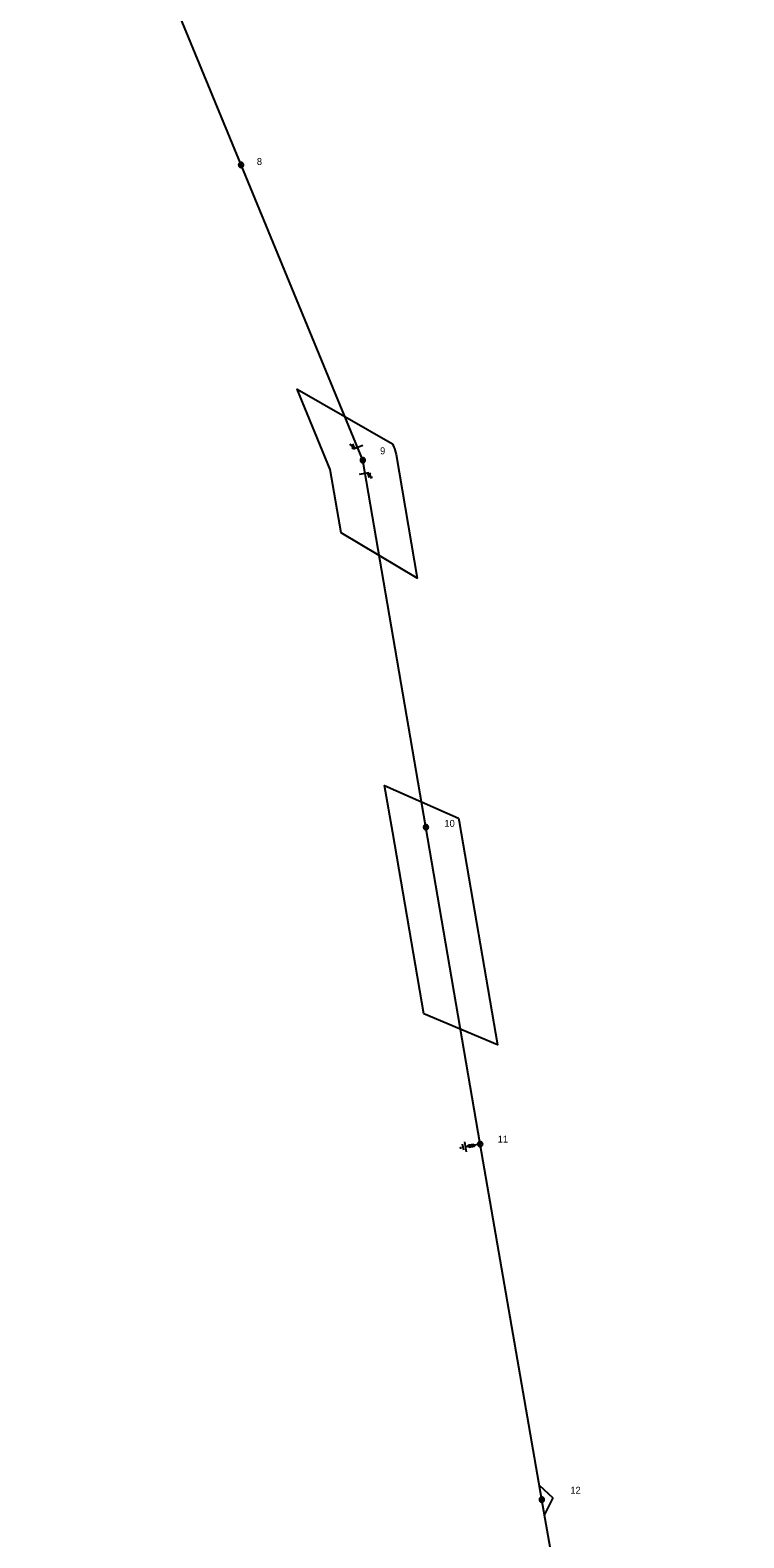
# Model space of a CAD drawing. Extents: x -788491 to -785797, y -1154753 to -1152002.
# Drawn here: x -786883.8 to -786703.8, y -1154288.7 to -1153908.5 of the extents above; entities that cross this region are included whole.
import ezdxf

# ---------------------------------------------------------------- set-up
doc = ezdxf.new("R2010")
doc.units = 0
for name, color, linetype in [('Vrstva 13', 7, 'Continuous'), ('Vrstva 14', 7, 'Continuous'), ('Vrstva 15', 7, 'Continuous'), ('Vrstva 16', 7, 'Continuous'), ('Vrstva 18', 7, 'Continuous'), ('Vrstva 2', 7, 'Continuous'), ('Vrstva 35', 7, 'Continuous'), ('Vrstva 52', 7, 'Continuous')]:
    doc.layers.add(name, color=color, linetype=linetype)

# ---------------------------------------------------------------- blocks, each defined once
blk = doc.blocks.new('VN840')
at = {"layer": 'Vrstva 15'}
for points in [[(-0.01, 1.41), (-0.01, -1.09)], [(-1.51, -1.24), (-1.51, -1.15)], [(-1.48, -1.35), (-1.51, -1.24)], [(-1.33, -1.42), (-1.48, -1.35)], [(-1.27, -1.42), (-1.33, -1.42)], [(-1.13, -1.35), (-1.27, -1.42)], [(-1.09, -1.24), (-1.13, -1.35)], [(-1.09, -0.59), (-1.09, -1.24)], [(-0.68, -0.59), (-0.68, -1.42)], [(-0.68, -1.11), (-0.27, -0.59)], [(-0.54, -0.94), (-0.2, -1.42)]]:
    blk.add_lwpolyline(points, dxfattribs=at)
blk = doc.blocks.new('VN860')
at = {"layer": 'Vrstva 15'}
for points in [[(-3.74, 0), (0.01, 2.82)], [(0.01, 2.82), (3.76, 0)]]:
    blk.add_lwpolyline(points, dxfattribs=at)
blk = doc.blocks.new('VN440')
at = {"layer": 'Vrstva 2'}
for points in [[(1.22, 0), (1.21, 0.13), (1.19, 0.25), (1.16, 0.38), (1.11, 0.5), (1.05, 0.61), (0.98, 0.72), (0.9, 0.82), (0.81, 0.91), (0.71, 0.99), (0.6, 1.06), (0.49, 1.12), (0.37, 1.16), (0.25, 1.2), (0.12, 1.22), (-0.01, 1.22), (-0.14, 1.22), (-0.26, 1.2), (-0.39, 1.16), (-0.51, 1.12), (-0.62, 1.06), (-0.73, 0.99), (-0.83, 0.91), (-0.92, 0.82), (-1, 0.72), (-1.07, 0.61), (-1.13, 0.5), (-1.18, 0.38), (-1.21, 0.25), (-1.23, 0.13), (-1.24, 0), (-1.23, -0.13), (-1.21, -0.26), (-1.18, -0.38), (-1.13, -0.5), (-1.07, -0.62), (-1, -0.73), (-0.92, -0.83), (-0.83, -0.92), (-0.73, -1), (-0.62, -1.07), (-0.51, -1.13), (-0.39, -1.17), (-0.26, -1.2), (-0.14, -1.23), (-0.01, -1.23), (0.12, -1.23), (0.25, -1.2), (0.37, -1.17), (0.49, -1.13), (0.6, -1.07), (0.71, -1), (0.81, -0.92), (0.9, -0.83), (0.98, -0.73), (1.05, -0.62), (1.11, -0.5), (1.16, -0.38), (1.19, -0.26), (1.21, -0.13), (1.22, 0)], [(-1.24, 0), (1.22, 0)], [(-1.18, -0.34), (1.1, -0.34)], [(-1.01, -0.63), (0.97, -0.63)], [(-0.74, -0.92), (0.68, -0.92)]]:
    blk.add_lwpolyline(points, dxfattribs=at)
blk = doc.blocks.new('VN820')
at = {"layer": 'Vrstva 13'}
for points in [[(0, 0), (0, -2.1)], [(-0.32, -1.63), (0.34, -1.63)], [(-0.32, -2.95), (-0.32, -1.63)], [(0.34, -2.95), (-0.32, -2.95)], [(0, -2.1), (-0.12, -1.86)], [(0, -2.1), (0.12, -1.86)], [(0, -2.95), (0, -3.75)], [(0.34, -1.63), (0.34, -2.95)]]:
    blk.add_lwpolyline(points, dxfattribs=at)
blk = doc.blocks.new('VN810')
at = {"layer": 'Vrstva 14'}
for points in [[(1.25, -3.75), (-1.25, -3.75)], [(0, -1.25), (0, -3.75)], [(0.77, -4.37), (-0.8, -4.37)], [(0, -5), (-0.25, -5)], [(0.27, -5), (0, -5)]]:
    blk.add_lwpolyline(points, dxfattribs=at)

msp = doc.modelspace()

# ---------------------------------------------------------------- linework, layer by layer
at = {"layer": 'Vrstva 35'}
for points in [[(-786792.43, -1154012.8), (-786792.06, -1154013.7), (-786791.93, -1154014.04), (-786791.54, -1154015.48), (-786786.17, -1154046.72), (-786805.39, -1154035.24), (-786808.13, -1154019.31), (-786816.49, -1153999.06)], [(-786775.77, -1154107.18), (-786775.62, -1154108.05), (-786765.97, -1154164.35), (-786784.56, -1154156.52), (-786792.37, -1154110.92), (-786794.43, -1154098.97)]]:
    msp.add_lwpolyline(points, close=True, dxfattribs=at)
at = {"layer": 'Vrstva 52'}
msp.add_lwpolyline([(-786703.8, -1154570.83), (-786716.28, -1154498.23), (-786728.41, -1154428.94), (-786740.19, -1154361.82), (-786754.76, -1154279.07), (-786770.29, -1154189.42), (-786783.99, -1154109.49), (-786799.92, -1154016.94), (-786830.62, -1153942.5), (-786855.4, -1153882.26), (-786883.82, -1153812.44)], dxfattribs=at)

# ---------------------------------------------------------------- block references
at = {"layer": 'Vrstva 13'}
for p, xscale, yscale, rotation in [((-786830.62, -1153942.5), 0.5000000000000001, 0.5, -66.97829163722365), ((-786799.92, -1154016.94), 0.5, 0.5000000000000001, 99.34559436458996), ((-786783.99, -1154109.49), 0.5000000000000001, 0.5, -79.32022497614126), ((-786770.29, -1154189.42), 0.49999999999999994, 0.5, -80.3236111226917), ((-786754.76, -1154279.07), 0.5, 0.5, -79.66151948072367)]:
    msp.add_blockref('VN440', p, dxfattribs=dict(at, xscale=xscale, yscale=yscale, rotation=rotation))
at = {"layer": 'Vrstva 15', "rotation": -79.51792778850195}
msp.add_blockref('VN810', (-786770.29, -1154189.41), dxfattribs=at)
at = {"layer": 'Vrstva 16', "rotation": -80.14212779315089}
msp.add_blockref('VN820', (-786770.29, -1154189.42), dxfattribs=at)
at = {"layer": 'Vrstva 18'}
for name, p, rotation in [('VN840', (-786801.22, -1154013.79), -67.58286672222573), ('VN840', (-786799.35, -1154020.21), 99.76345556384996), ('VN860', (-786754.76, -1154279.07), -79.75039453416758)]:
    msp.add_blockref(name, p, dxfattribs=dict(at, rotation=rotation))

# ---------------------------------------------------------------- texts
at = {"layer": 'Vrstva 14'}
for s, p in [('8', (-786826.64, -1153942.49)), ('9', (-786795.56, -1154015.46)), ('10', (-786779.32, -1154109.4)), ('11', (-786765.87, -1154189.02)), ('12', (-786747.56, -1154277.57))]:
    msp.add_text(s, height=1.75, dxfattribs=at).set_placement(p)

doc.saveas('drawing.dxf')
